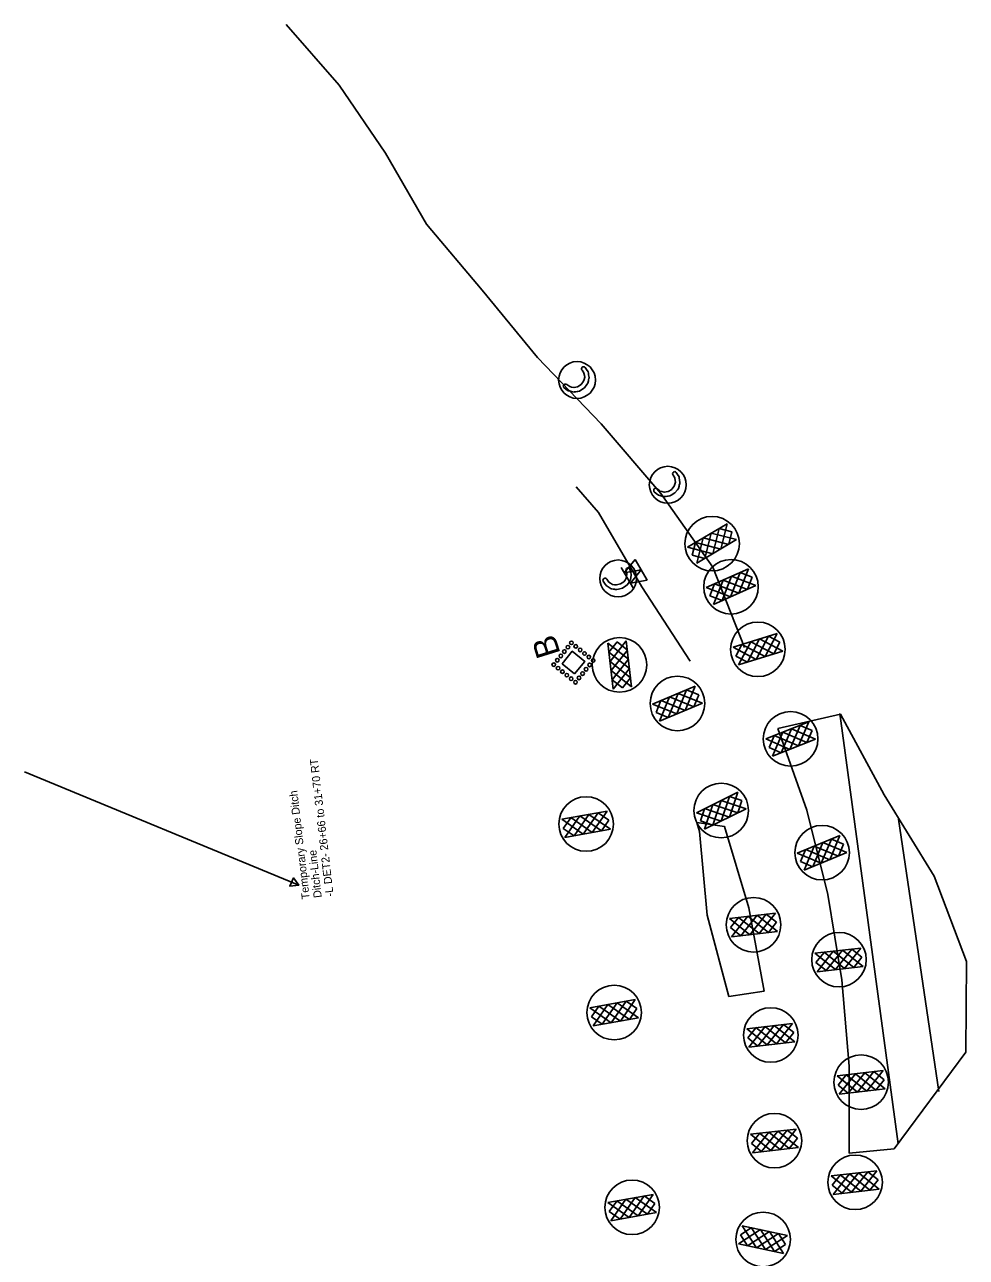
# Model space of a CAD drawing. Extents: x 400935 to 481562, y 415700 to 505362.
# Drawn here: x 474156 to 474744, y 504592 to 505362 of the extents above; entities that cross this region are included whole.
import ezdxf

# ---------------------------------------------------------------- set-up
doc = ezdxf.new("R2010")
doc.units = 0
for name, color, linetype in [('Coir Fiber Wattle with PAM Final CELL', 7, 'Continuous'), ('Excelsior Wattle Line Style Final', 7, 'Continuous'), ('Label B Both CELL', 7, 'Continuous'), ('Matting on Slope Note Final CELL', 7, 'Continuous'), ('Rock Inlet Sediment Trap Type B Both CELL', 7, 'Continuous'), ('Rock Silt Check Type A with Matting and PAM CG CELL', 7, 'Continuous'), ('Rock Silt Check Type A with Matting and PAM Final CELL', 7, 'Continuous'), ('Scratch_Level_3', 7, 'Continuous'), ('Special Sediment Control Fence Section CG CELL', 7, 'Continuous'), ('Temporary Silt Fence CG', 7, 'Continuous')]:
    doc.layers.add(name, color=color, linetype=linetype)

msp = doc.modelspace()

# ---------------------------------------------------------------- linework, layer by layer
at = {"layer": 'Coir Fiber Wattle with PAM Final CELL'}
for p, q in [((474505.25, 505144.93), (474504.25, 505146.5)), ((474505.22, 505139.62), (474505.53, 505140.79)), ((474505.25, 505144.93), (474505.43, 505144.65)), ((474505.7, 505143.19), (474505.43, 505144.65)), ((474505.53, 505140.79), (474505.89, 505142.18)), ((474505.89, 505142.18), (474505.7, 505143.19)), ((474494.62, 505137.61), (474495.87, 505136.69)), ((474495.87, 505136.69), (474496.51, 505136.22)), ((474496.51, 505136.22), (474497.58, 505135.97)), ((474497.58, 505135.97), (474498.99, 505135.64)), ((474499.22, 505135.68), (474498.99, 505135.64)), ((474499.22, 505135.68), (474500.31, 505135.9)), ((474501.48, 505136.14), (474500.31, 505135.9)), ((474501.48, 505136.14), (474503.68, 505137.58)), ((474503.69, 505137.59), (474503.68, 505137.58)), ((474503.69, 505137.59), (474505.22, 505139.62)), ((474562.07, 505079.36), (474561.13, 505080.96)), ((474562.07, 505079.36), (474562.24, 505079.07)), ((474562.46, 505077.61), (474562.24, 505079.07)), ((474551.18, 505072.43), (474552.39, 505071.46)), ((474552.39, 505071.46), (474553.01, 505070.97)), ((474553.01, 505070.97), (474554.08, 505070.68)), ((474557.98, 505070.71), (474560.23, 505072.07)), ((474560.24, 505072.08), (474560.23, 505072.07)), ((474560.24, 505072.08), (474561.84, 505074.06)), ((474561.84, 505074.06), (474562.19, 505075.21)), ((474562.19, 505075.21), (474562.61, 505076.59)), ((474562.61, 505076.59), (474562.46, 505077.61)), ((474554.08, 505070.68), (474555.48, 505070.3)), ((474555.71, 505070.33), (474555.48, 505070.3)), ((474555.71, 505070.33), (474556.81, 505070.52)), ((474557.98, 505070.71), (474556.81, 505070.52)), ((474532.18, 505019.39), (474531.75, 505021.2)), ((474531.88, 505016.58), (474532.04, 505017.6)), ((474532.04, 505017.6), (474532.26, 505019.06)), ((474532.18, 505019.39), (474532.26, 505019.06)), ((474519.73, 505015.97), (474520.61, 505014.69)), ((474520.61, 505014.69), (474521.05, 505014.04)), ((474521.05, 505014.04), (474521.99, 505013.45)), ((474521.99, 505013.45), (474523.21, 505012.67)), ((474523.44, 505012.64), (474523.21, 505012.67)), ((474523.44, 505012.64), (474524.55, 505012.49)), ((474525.73, 505012.33), (474524.55, 505012.49)), ((474525.73, 505012.33), (474528.28, 505012.97)), ((474528.29, 505012.97), (474528.28, 505012.97)), ((474528.29, 505012.97), (474530.4, 505014.39)), ((474530.4, 505014.39), (474531.07, 505015.38)), ((474531.07, 505015.38), (474531.88, 505016.58))]:
    msp.add_line(p, q, dxfattribs=at)
for points in [[(474506.14, 505148.28), (474507, 505146.98), (474508, 505145.46), (474508.16, 505144.64), (474508.35, 505143.65), (474508.68, 505141.89), (474508.67, 505141.85), (474508.57, 505141.42), (474508.55, 505141.34), (474508.33, 505140.41), (474508.18, 505139.77), (474507.83, 505138.34), (474507.22, 505137.5), (474505.73, 505135.43), (474505.72, 505135.42), (474503.5, 505134), (474502.63, 505133.45), (474501.51, 505133.26), (474501.28, 505133.22), (474500.33, 505133.05), (474499.61, 505132.93), (474499.44, 505132.9), (474499.08, 505132.84), (474499.08, 505132.84), (474497.61, 505133.2), (474496.31, 505133.52), (474495.52, 505133.71), (474494.09, 505134.74), (474492.83, 505135.64)], [(474563.08, 505082.67), (474563.89, 505081.34), (474564.84, 505079.79), (474564.96, 505078.97), (474565.12, 505077.97), (474565.39, 505076.19), (474565.38, 505076.15), (474565.26, 505075.73), (474565.24, 505075.66), (474564.98, 505074.73), (474564.8, 505074.09), (474564.41, 505072.68), (474563.77, 505071.86), (474562.2, 505069.85), (474562.19, 505069.84), (474559.92, 505068.5), (474559.03, 505067.98), (474557.91, 505067.83), (474557.68, 505067.8), (474556.72, 505067.67), (474556, 505067.57), (474555.83, 505067.55), (474555.47, 505067.5), (474555.46, 505067.5), (474554.01, 505067.91), (474552.72, 505068.28), (474551.94, 505068.5), (474550.55, 505069.58), (474549.32, 505070.52)], [(474534.12, 505022.26), (474534.5, 505020.75), (474534.95, 505018.99), (474534.83, 505018.16), (474534.68, 505017.16), (474534.42, 505015.39), (474534.4, 505015.35), (474534.16, 505014.98), (474534.12, 505014.92), (474533.6, 505014.11), (474533.24, 505013.55), (474532.45, 505012.32), (474531.6, 505011.72), (474529.5, 505010.26), (474529.49, 505010.26), (474526.93, 505009.65), (474525.93, 505009.41), (474524.81, 505009.6), (474524.57, 505009.63), (474523.63, 505009.79), (474522.91, 505009.91), (474522.74, 505009.94), (474522.37, 505010), (474522.37, 505010), (474521.1, 505010.83), (474519.98, 505011.56), (474519.3, 505012), (474518.29, 505013.44), (474517.4, 505014.7)]]:
    msp.add_lwpolyline(points, dxfattribs=at)
for centre in [(474501.09, 505140.37), (474557.74, 505074.95), (474526.75, 505016.45)]:
    msp.add_circle(centre, 11.5, dxfattribs=at)
for centre, radius, start, end in [((474505.19, 505147.39), 1.3, 43.37091, 223.37091), ((474493.8, 505136.55), 1.33, 52.25827, 223.37091), ((474562.1, 505081.82), 1.3, 41.29047, 221.29047), ((474550.32, 505071.4), 1.33, 50.17784, 221.29047), ((474532.94, 505021.73), 1.3, 24.15204, 204.15204), ((474518.61, 505015.25), 1.33, 33.03941, 204.15204)]:
    msp.add_arc(centre, radius, start, end, dxfattribs=at)
at = {"layer": 'Excelsior Wattle Line Style Final'}
for p, q in [((474701.68, 504663.15), (474665.23, 504931.98)), ((474727.16, 504695.88), (474701.97, 504866.05))]:
    msp.add_line(p, q, dxfattribs=at)
at = {"layer": 'Matting on Slope Note Final CELL'}
for p, q in [((474665.67, 504931.7), (474626.54, 504922.75)), ((474692.89, 504881.18), (474665.67, 504931.7)), ((474724.25, 504830.51), (474692.89, 504881.18)), ((474593.3, 504861.45), (474575.86, 504863.86)), ((474575.86, 504863.86), (474577.48, 504858.31)), ((474593.3, 504861.45), (474593.3, 504861.45)), ((474593.3, 504861.45), (474593.3, 504861.45)), ((474744.26, 504777.05), (474724.25, 504830.51)), ((474743.93, 504720.52), (474744.26, 504777.05)), ((474595.92, 504755.35), (474617.92, 504758.57)), ((474699.17, 504660.12), (474743.93, 504720.52))]:
    msp.add_line(p, q, dxfattribs=at)
for points in [[(474626.54, 504922.75), (474644.56, 504871.6), (474657.74, 504819.07), (474666.52, 504765.68), (474670.97, 504711.72), (474671.03, 504657.44), (474699.17, 504660.12)], [(474577.48, 504858.31), (474582.34, 504806.09), (474595.92, 504755.35)], [(474617.92, 504758.57), (474608.42, 504810.58), (474593.3, 504861.45)]]:
    msp.add_lwpolyline(points, dxfattribs=at)
msp.add_lwpolyline([(474617.92, 504758.57), (474608.42, 504810.58), (474593.3, 504861.45), (474575.86, 504863.86), (474577.48, 504858.31), (474582.34, 504806.09), (474595.92, 504755.35)], close=True, dxfattribs=at)
at = {"layer": 'Rock Inlet Sediment Trap Type B Both CELL'}
msp.add_lwpolyline([(474499.59, 504956.84), (474491.83, 504963.15), (474498.13, 504970.91), (474505.89, 504964.6)], close=True, dxfattribs=at)
for centre in [(474493.17, 504970.74), (474495.37, 504973.46), (474497.58, 504976.17), (474500.3, 504973.97), (474503.02, 504971.76), (474505.73, 504969.55), (474486.55, 504962.59), (474488.76, 504965.3), (474490.96, 504968.02), (474508.45, 504967.35), (474508.96, 504962.42), (474511.17, 504965.14), (474489.27, 504960.38), (474491.98, 504958.17), (474494.7, 504955.97), (474502.34, 504954.27), (474504.55, 504956.99), (474506.75, 504959.71), (474497.42, 504953.76), (474500.14, 504951.56)]:
    msp.add_circle(centre, 1.12, dxfattribs=at)
at = {"layer": 'Rock Silt Check Type A with Matting and PAM CG CELL'}
for p, q in [((474491.49, 504865.96), (474519.93, 504871.11)), ((474519.93, 504871.11), (474510.62, 504857.69)), ((474504.91, 504856.65), (474491.49, 504865.96)), ((474497.11, 504866.93), (474492.5, 504860.3)), ((474502.85, 504868.02), (474493.54, 504854.6)), ((474510.62, 504857.69), (474497.15, 504866.99)), ((474508.56, 504869.05), (474499.2, 504855.62)), ((474516.27, 504858.71), (474502.85, 504868.02)), ((474514.22, 504870.09), (474504.91, 504856.65)), ((474521.98, 504859.74), (474508.56, 504869.05)), ((474520.96, 504865.45), (474514.22, 504870.09)), ((474520.96, 504865.45), (474516.27, 504858.71)), ((474499.2, 504855.62), (474492.5, 504860.3)), ((474493.54, 504854.6), (474521.98, 504859.74)), ((474509.02, 504748.22), (474537.46, 504753.36)), ((474522.44, 504738.91), (474509.02, 504748.22)), ((474514.64, 504749.18), (474510.03, 504742.56)), ((474520.39, 504750.27), (474511.08, 504736.85)), ((474528.15, 504739.94), (474514.68, 504749.24)), ((474526.1, 504751.31), (474516.74, 504737.88)), ((474533.81, 504740.96), (474520.39, 504750.27)), ((474531.75, 504752.34), (474522.44, 504738.91)), ((474539.52, 504742), (474526.1, 504751.31)), ((474537.46, 504753.36), (474528.15, 504739.94)), ((474538.5, 504747.71), (474531.75, 504752.34)), ((474538.5, 504747.71), (474533.81, 504740.96)), ((474516.74, 504737.88), (474510.03, 504742.56)), ((474511.08, 504736.85), (474539.52, 504742)), ((474520.24, 504626.52), (474548.68, 504631.67)), ((474533.66, 504617.22), (474520.24, 504626.52)), ((474525.86, 504627.49), (474521.25, 504620.86)), ((474531.6, 504628.58), (474522.29, 504615.16)), ((474539.37, 504618.25), (474525.9, 504627.55)), ((474537.31, 504629.61), (474527.95, 504616.18)), ((474545.03, 504619.27), (474531.6, 504628.58)), ((474542.97, 504630.65), (474533.66, 504617.22)), ((474550.73, 504620.3), (474537.31, 504629.61)), ((474548.68, 504631.67), (474539.37, 504618.25)), ((474549.71, 504626.01), (474542.97, 504630.65)), ((474549.71, 504626.01), (474545.03, 504619.27)), ((474527.95, 504616.18), (474521.25, 504620.86)), ((474522.29, 504615.16), (474550.73, 504620.3))]:
    msp.add_line(p, q, dxfattribs=at)
for centre in [(474506.75, 504862.99), (474524.29, 504745.24), (474535.5, 504623.55)]:
    msp.add_circle(centre, 17.04, dxfattribs=at)
at = {"layer": 'Rock Silt Check Type A with Matting and PAM Final CELL'}
for p, q in [((474594.9, 505050.59), (474570.03, 505035.87)), ((474585.85, 505031.81), (474589.95, 505047.66)), ((474589.95, 505047.66), (474597.87, 505045.6)), ((474590.84, 505034.76), (474594.9, 505050.59)), ((474575.91, 505025.93), (474579.97, 505041.75)), ((474600.78, 505040.64), (474575.91, 505025.93)), ((474579.97, 505041.75), (474595.83, 505037.72)), ((474580.91, 505028.87), (474584.96, 505044.7)), ((474584.96, 505044.7), (474600.78, 505040.64)), ((474595.85, 505037.79), (474597.87, 505045.6)), ((474570.03, 505035.87), (474585.85, 505031.81)), ((474572.97, 505030.87), (474575.02, 505038.82)), ((474575.02, 505038.82), (474590.84, 505034.76)), ((474572.97, 505030.87), (474580.91, 505028.87)), ((474608.13, 505022.47), (474581.71, 505010.76)), ((474591.7, 505002.54), (474597.57, 505017.79)), ((474596.95, 505004.88), (474602.88, 505020.14)), ((474597.57, 505017.79), (474612.81, 505011.91)), ((474602.25, 505007.23), (474608.13, 505022.47)), ((474602.88, 505020.14), (474610.49, 505017.17)), ((474607.58, 505009.64), (474610.49, 505017.17)), ((474581.71, 505010.76), (474596.95, 505004.88)), ((474584.05, 505005.45), (474587.01, 505013.11)), ((474586.39, 505000.2), (474592.27, 505015.44)), ((474612.81, 505011.91), (474586.39, 505000.2)), ((474587.01, 505013.11), (474602.25, 505007.23)), ((474592.27, 505015.44), (474607.56, 505009.58)), ((474584.05, 505005.45), (474591.7, 505002.54)), ((474626.11, 504982.07), (474598.53, 504973.43)), ((474607.52, 504964.13), (474615.08, 504978.62)), ((474613, 504965.86), (474620.62, 504980.35)), ((474615.08, 504978.62), (474629.56, 504971.05)), ((474618.54, 504967.6), (474626.11, 504982.07)), ((474620.62, 504980.35), (474627.85, 504976.54)), ((474523.67, 504947.35), (474520.38, 504976.06)), ((474520.38, 504976.06), (474533.17, 504965.9)), ((474526.09, 504976.73), (474521.03, 504970.3)), ((474531.85, 504977.38), (474521.69, 504964.59)), ((474532.51, 504971.62), (474522.36, 504958.82)), ((474526.09, 504976.73), (474532.51, 504971.62)), ((474535.15, 504948.67), (474531.85, 504977.38)), ((474598.53, 504973.43), (474613, 504965.86)), ((474600.25, 504967.89), (474604.06, 504975.17)), ((474601.98, 504962.41), (474609.55, 504976.88)), ((474629.56, 504971.05), (474601.98, 504962.41)), ((474604.06, 504975.17), (474618.54, 504967.6)), ((474609.55, 504976.88), (474624.07, 504969.33)), ((474624.1, 504969.39), (474627.85, 504976.54)), ((474521.03, 504970.3), (474533.83, 504960.14)), ((474521.69, 504964.59), (474534.49, 504954.38)), ((474533.17, 504965.9), (474523.02, 504953.06)), ((474600.25, 504967.89), (474607.52, 504964.13)), ((474522.36, 504958.82), (474535.15, 504948.67)), ((474533.83, 504960.14), (474523.67, 504947.35)), ((474523.07, 504953.02), (474529.39, 504947.99)), ((474534.49, 504954.38), (474529.39, 504947.99)), ((474548.24, 504937.97), (474574.92, 504949.08)), ((474574.92, 504949.08), (474568.7, 504933.98)), ((474553.52, 504940.11), (474550.44, 504932.66)), ((474558.9, 504942.41), (474552.68, 504927.31)), ((474568.7, 504933.98), (474553.55, 504940.18)), ((474564.25, 504944.64), (474557.99, 504929.52)), ((474574, 504936.19), (474558.9, 504942.41)), ((474569.56, 504946.86), (474563.34, 504931.75)), ((474579.36, 504938.42), (474564.25, 504944.64)), ((474577.14, 504943.78), (474569.56, 504946.86)), ((474577.14, 504943.78), (474574, 504936.19)), ((474563.34, 504931.75), (474548.24, 504937.97)), ((474557.99, 504929.52), (474550.44, 504932.66)), ((474552.68, 504927.31), (474579.36, 504938.42)), ((474618.93, 504916.12), (474645.8, 504926.76)), ((474640.4, 504924.64), (474633.92, 504909.64)), ((474645.8, 504926.76), (474639.32, 504911.77)), ((474647.93, 504921.42), (474640.4, 504924.64)), ((474624.25, 504918.18), (474621.04, 504910.77)), ((474629.67, 504920.38), (474623.18, 504905.39)), ((474639.32, 504911.77), (474624.28, 504918.24)), ((474635.06, 504922.51), (474628.53, 504907.5)), ((474644.66, 504913.89), (474629.67, 504920.38)), ((474650.05, 504916.03), (474635.06, 504922.51)), ((474647.93, 504921.42), (474644.66, 504913.89)), ((474633.92, 504909.64), (474618.93, 504916.12)), ((474628.53, 504907.5), (474621.04, 504910.77)), ((474623.18, 504905.39), (474650.05, 504916.03)), ((474575.65, 504870.06), (474601.56, 504882.85)), ((474596.35, 504880.3), (474591.12, 504864.82)), ((474601.56, 504882.85), (474596.32, 504867.38)), ((474604.12, 504877.7), (474596.35, 504880.3)), ((474580.78, 504872.54), (474578.18, 504864.9)), ((474586, 504875.17), (474580.76, 504859.7)), ((474580.76, 504859.7), (474606.67, 504872.5)), ((474596.32, 504867.38), (474580.8, 504872.6)), ((474591.2, 504877.74), (474585.92, 504862.25)), ((474601.47, 504869.93), (474586, 504875.17)), ((474606.67, 504872.5), (474591.2, 504877.74)), ((474604.12, 504877.7), (474601.47, 504869.93)), ((474591.12, 504864.82), (474575.65, 504870.06)), ((474585.92, 504862.25), (474578.18, 504864.9)), ((474638.58, 504844.82), (474665.31, 504855.8)), ((474665.31, 504855.8), (474659.02, 504840.73)), ((474649.27, 504849.21), (474642.97, 504834.14)), ((474654.63, 504851.41), (474648.29, 504836.32)), ((474664.34, 504842.92), (474649.27, 504849.21)), ((474659.95, 504853.61), (474653.66, 504838.53)), ((474669.71, 504845.12), (474654.63, 504851.41)), ((474667.51, 504850.49), (474659.95, 504853.61)), ((474667.51, 504850.49), (474664.34, 504842.92)), ((474653.66, 504838.53), (474638.58, 504844.82)), ((474643.88, 504846.94), (474640.76, 504839.5)), ((474642.97, 504834.14), (474669.71, 504845.12)), ((474659.02, 504840.73), (474643.9, 504847)), ((474648.29, 504836.32), (474640.76, 504839.5)), ((474596.32, 504804.03), (474625.03, 504807.33)), ((474609.12, 504793.88), (474596.32, 504804.03)), ((474601.99, 504804.64), (474596.97, 504798.32)), ((474607.8, 504805.35), (474597.64, 504792.56)), ((474614.88, 504794.54), (474602.04, 504804.69)), ((474613.56, 504806.02), (474603.35, 504793.22)), ((474620.59, 504795.2), (474607.8, 504805.35)), ((474619.27, 504806.68), (474609.12, 504793.88)), ((474626.35, 504795.86), (474613.56, 504806.02)), ((474625.03, 504807.33), (474614.88, 504794.54)), ((474625.7, 504801.62), (474619.27, 504806.68)), ((474625.7, 504801.62), (474620.59, 504795.2)), ((474603.35, 504793.22), (474596.97, 504798.32)), ((474597.64, 504792.56), (474626.35, 504795.86)), ((474649.68, 504782.23), (474678.39, 504785.53)), ((474662.47, 504772.08), (474649.68, 504782.23)), ((474655.35, 504782.84), (474650.32, 504776.52)), ((474661.15, 504783.55), (474651, 504770.76)), ((474668.23, 504772.74), (474655.39, 504782.89)), ((474666.91, 504784.22), (474656.71, 504771.42)), ((474673.95, 504773.4), (474661.15, 504783.55)), ((474672.63, 504784.88), (474662.47, 504772.08)), ((474679.71, 504774.06), (474666.91, 504784.22)), ((474678.39, 504785.53), (474668.23, 504772.74)), ((474679.06, 504779.82), (474672.63, 504784.88)), ((474679.06, 504779.82), (474673.95, 504773.4)), ((474656.71, 504771.42), (474650.32, 504776.52)), ((474651, 504770.76), (474679.71, 504774.06)), ((474607.06, 504735.14), (474635.77, 504738.44)), ((474619.85, 504724.99), (474607.06, 504735.14)), ((474612.73, 504735.74), (474607.7, 504729.43)), ((474618.53, 504736.46), (474608.38, 504723.67)), ((474625.61, 504725.65), (474612.77, 504735.8)), ((474624.3, 504737.12), (474614.09, 504724.33)), ((474631.33, 504726.31), (474618.53, 504736.46)), ((474630.01, 504737.79), (474619.85, 504724.99)), ((474637.09, 504726.97), (474624.3, 504737.12)), ((474635.77, 504738.44), (474625.61, 504725.65)), ((474636.44, 504732.73), (474630.01, 504737.79)), ((474636.44, 504732.73), (474631.33, 504726.31)), ((474614.09, 504724.33), (474607.7, 504729.43)), ((474608.38, 504723.67), (474637.09, 504726.97)), ((474663.51, 504705.69), (474692.22, 504708.98)), ((474692.22, 504708.98), (474682.06, 504696.19)), ((474676.3, 504695.53), (474663.51, 504705.69)), ((474669.18, 504706.29), (474664.15, 504699.97)), ((474674.98, 504707), (474664.83, 504694.21)), ((474682.06, 504696.19), (474669.22, 504706.34)), ((474680.75, 504707.67), (474670.54, 504694.87)), ((474687.78, 504696.85), (474674.98, 504707)), ((474686.46, 504708.34), (474676.3, 504695.53)), ((474693.54, 504697.51), (474680.75, 504707.67)), ((474692.89, 504703.27), (474686.46, 504708.34)), ((474692.89, 504703.27), (474687.78, 504696.85)), ((474670.54, 504694.87), (474664.15, 504699.97)), ((474664.83, 504694.21), (474693.54, 504697.51)), ((474609.35, 504669.16), (474638.06, 504672.46)), ((474620.82, 504670.48), (474610.67, 504657.68)), ((474626.59, 504671.14), (474616.38, 504658.34)), ((474633.62, 504660.32), (474620.82, 504670.48)), ((474632.3, 504671.81), (474622.14, 504659)), ((474639.38, 504660.98), (474626.59, 504671.14)), ((474638.06, 504672.46), (474627.9, 504659.66)), ((474638.73, 504666.75), (474632.3, 504671.81)), ((474622.14, 504659), (474609.35, 504669.16)), ((474615.02, 504669.76), (474609.99, 504663.45)), ((474616.38, 504658.34), (474609.99, 504663.45)), ((474627.9, 504659.66), (474615.06, 504669.82)), ((474638.73, 504666.75), (474633.62, 504660.32)), ((474610.67, 504657.68), (474639.38, 504660.98)), ((474659.72, 504643.14), (474688.43, 504646.44)), ((474672.51, 504632.98), (474659.72, 504643.14)), ((474665.39, 504643.74), (474660.36, 504637.42)), ((474671.2, 504644.46), (474661.04, 504631.66)), ((474678.28, 504633.64), (474665.43, 504643.79)), ((474676.96, 504645.12), (474666.75, 504632.32)), ((474683.99, 504634.3), (474671.2, 504644.46)), ((474682.67, 504645.79), (474672.51, 504632.98)), ((474689.75, 504634.96), (474676.96, 504645.12)), ((474688.43, 504646.44), (474678.28, 504633.64)), ((474689.1, 504640.72), (474682.67, 504645.79)), ((474689.1, 504640.72), (474683.99, 504634.3)), ((474666.75, 504632.32), (474660.36, 504637.42)), ((474661.04, 504631.66), (474689.75, 504634.96)), ((474615.62, 504609.64), (474601.89, 504600.79)), ((474609.89, 504610.82), (474603.11, 504606.46)), ((474604.33, 504612.08), (474632.58, 504605.97)), ((474613.18, 504598.35), (474604.33, 504612.08)), ((474618.85, 504597.12), (474609.95, 504610.86)), ((474624.47, 504595.91), (474615.62, 504609.64)), ((474607.51, 504599.57), (474603.11, 504606.46)), ((474621.29, 504608.41), (474607.51, 504599.57)), ((474626.91, 504607.21), (474613.18, 504598.35)), ((474632.58, 504605.97), (474618.85, 504597.12)), ((474630.14, 504594.68), (474621.29, 504608.41)), ((474631.38, 504600.35), (474626.91, 504607.21)), ((474601.89, 504600.79), (474630.14, 504594.68)), ((474631.38, 504600.35), (474624.47, 504595.91))]:
    msp.add_line(p, q, dxfattribs=at)
for centre in [(474585.43, 505038.13), (474597.28, 505011.2), (474614.04, 504972.11), (474527.63, 504962.39), (474563.79, 504938.33), (474634.49, 504916.21), (474591.14, 504871.41), (474654.14, 504845.1), (474611.37, 504800.08), (474664.72, 504778.28), (474622.1, 504731.19), (474678.55, 504701.73), (474624.39, 504665.2), (474674.76, 504639.18), (474617.3, 504603.5)]:
    msp.add_circle(centre, 17.04, dxfattribs=at)
at = {"layer": 'Scratch_Level_3'}
msp.add_lwpolyline([(474156.06, 504895.57), (474327.22, 504824.71), (474321.6, 504824.2), (474324.07, 504829.29), (474327.22, 504824.71)], dxfattribs=at)
at = {"layer": 'Special Sediment Control Fence Section CG CELL'}
for p, q in [((474544.94, 505015.28), (474537.37, 505028.23)), ((474536.31, 505010.23), (474528.73, 505023.18))]:
    msp.add_line(p, q, dxfattribs=at)
for points in [[(474541.15, 505021.76), (474530.63, 505019.95), (474537.37, 505028.23)], [(474544.94, 505015.28), (474534.41, 505013.47), (474541.15, 505021.76)]]:
    msp.add_lwpolyline(points, dxfattribs=at)
at = {"layer": 'Temporary Silt Fence CG'}
for points in [[(474605.79, 504973.21), (474585.99, 505023.48), (474553.48, 505069.56), (474516.1, 505113.03), (474476.32, 505154.43), (474441.74, 505196.58), (474406.97, 505237.69), (474381.44, 505282.13), (474352.42, 505324.57), (474319.51, 505362.36)], [(474571.81, 504964.68), (474541.52, 505011.08), (474514.45, 505057.56), (474500.52, 505073.67)]]:
    msp.add_lwpolyline(points, dxfattribs=at)

# ---------------------------------------------------------------- texts
at = {"layer": 'Label B Both CELL'}
msp.add_text('B', height=15, rotation=107.39476, dxfattribs=at).set_placement((474490.88, 504969.53))
at = {"layer": 'Scratch_Level_3'}
for s, p in [('-L DET2- 26+66 to 31+70 RT', (474349.09, 504818.01)), ('Temporary Slope Ditch', (474334.19, 504816.29)), ('Ditch-Line', (474341.64, 504817.15))]:
    msp.add_text(s, height=5, rotation=96.60736, dxfattribs=at).set_placement(p)

doc.saveas('drawing.dxf')
